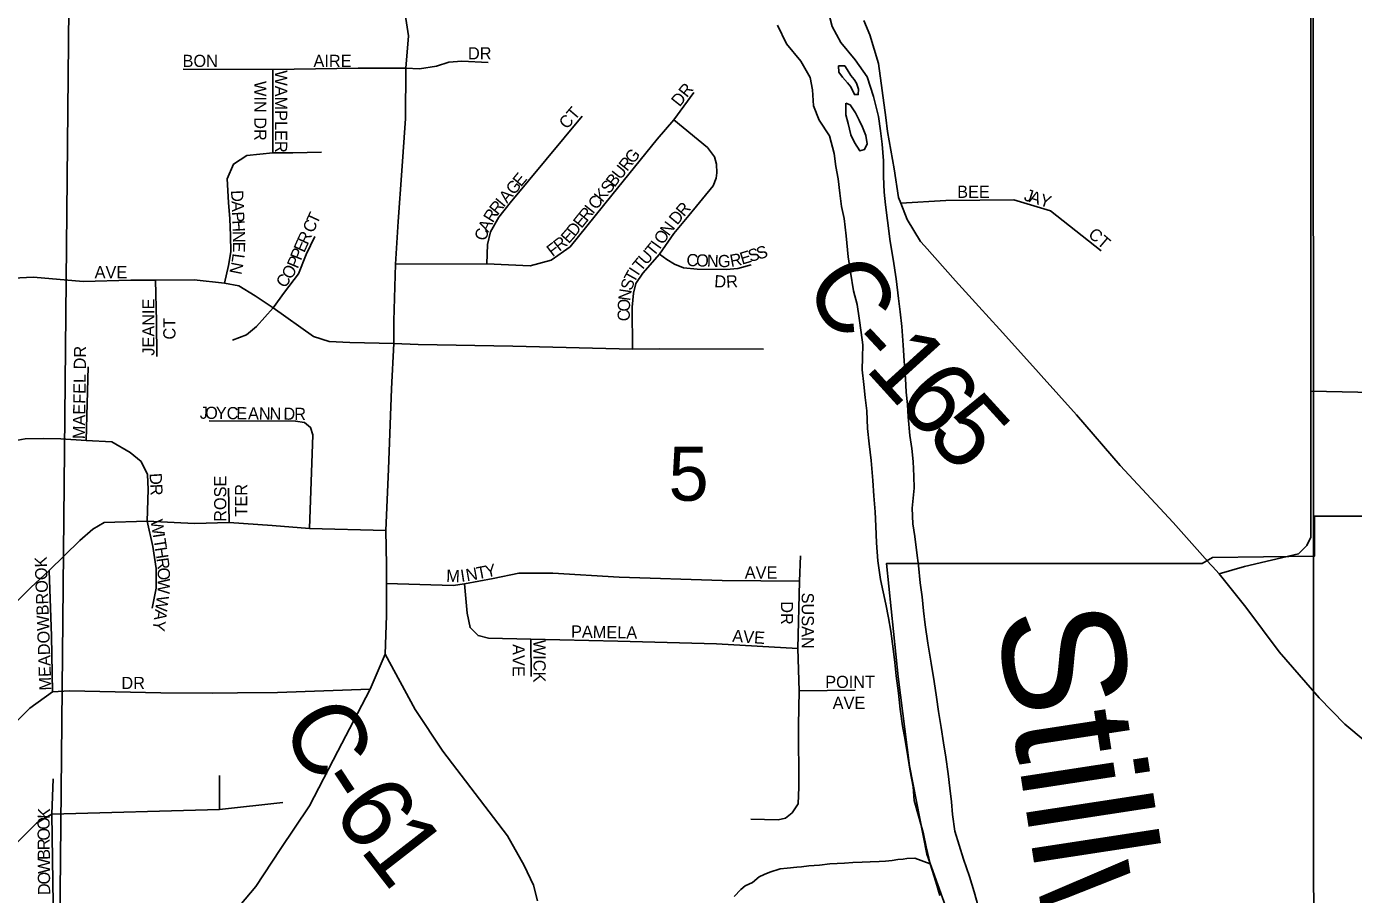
# Model space of a CAD drawing. Extents: x 8.5 to 81.5, y -1.2 to 22.4.
# Drawn here: x 50.196 to 51.227, y 14.998 to 15.672 of the extents above; entities that cross this region are included whole.
import ezdxf

# ---------------------------------------------------------------- set-up
doc = ezdxf.new("R2010")
doc.units = 0
for name, color, linetype in [('GM_X_City_Street', 7, 'Continuous'), ('GM_X_Corporation', 7, 'Continuous'), ('GM_X_County_Road', 7, 'Continuous'), ('GM_X_County_Road_Text', 7, 'Continuous'), ('GM_X_Major_River', 7, 'Continuous'), ('GM_X_Major_River_Text', 7, 'Continuous'), ('GM_X_Minor_River', 7, 'Continuous'), ('GM_X_Section', 7, 'Continuous'), ('GM_X_Section_Text', 7, 'Continuous'), ('GM_X_Township_Road', 7, 'Continuous'), ('GM_X_Township_Subdivision', 7, 'Continuous'), ('GM_X_Township_Subdivision_Text', 7, 'Continuous')]:
    doc.layers.add(name, color=color, linetype=linetype)

msp = doc.modelspace()

# ---------------------------------------------------------------- linework, layer by layer
at = {"layer": 'GM_X_City_Street'}
for points in [[(51.1225, 15.2467), (51.1422, 15.2526), (51.1841, 15.2623), (51.1905, 15.2688), (51.1938, 15.2752), (51.1938, 15.2951), (51.1938, 15.297)], [(51.3735, 15.004), (51.373, 15.0044), (51.3347, 15.0342), (51.3066, 15.0568), (51.27, 15.0866), (51.2359, 15.1168), (51.2201, 15.13), (51.2001, 15.1505), (51.169, 15.1863), (51.1432, 15.2208), (51.1225, 15.2467), (51.1174, 15.2524)]]:
    msp.add_lwpolyline(points, dxfattribs=at)
at = {"layer": 'GM_X_Corporation'}
msp.add_lwpolyline([(51.2945, 15.2917), (51.1966, 15.2917), (51.1966, 15.2606), (51.1174, 15.2595), (51.1092, 15.2548), (50.864, 15.2548), (50.8731, 15.1668), (50.882, 15.0975), (50.8955, 15.0291), (50.9111, 14.985), (50.9207, 14.9475), (50.9238, 14.8897), (50.9254, 14.8296), (50.9211, 14.7826), (50.9101, 14.7376), (50.8975, 14.7193), (50.9131, 14.6619), (50.936, 14.6195), (50.9623, 14.5808), (50.9931, 14.55), (51.0319, 14.511), (51.0505, 14.482), (51.0628, 14.457), (51.0687, 14.4506)], dxfattribs=at)
at = {"layer": 'GM_X_County_Road'}
for points in [[(50.3452, 14.9693), (50.3741, 15.0038), (50.393, 15.0327), (50.4158, 15.0666), (50.438, 15.1089), (50.4531, 15.1383), (50.4631, 15.1572), (50.4747, 15.1845), (50.4756, 15.2145), (50.4756, 15.2394), (50.4756, 15.2537), (50.4751, 15.2804), (50.4773, 15.328), (50.4796, 15.3905), (50.4813, 15.4257), (50.4813, 15.4434), (50.4826, 15.4873), (50.4848, 15.5206), (50.4876, 15.5599), (50.4904, 15.6006), (50.4908, 15.6397), (50.4928, 15.6648), (50.4871, 15.7022)], [(50.8935, 15.5017), (50.8905, 15.5051), (50.8802, 15.5222), (50.8752, 15.5348), (50.8734, 15.5393), (50.87, 15.5615), (50.8649, 15.5905), (50.8635, 15.6013), (50.858, 15.6434), (50.8512, 15.6656), (50.8465, 15.6767)], [(50.9802, 15.4056), (50.9519, 15.4369), (50.9358, 15.4545), (50.9178, 15.4744), (50.8935, 15.5017)], [(51.1174, 15.2524), (51.1158, 15.2541), (51.0867, 15.2867), (51.0457, 15.331), (51.0116, 15.3703), (50.9843, 15.401), (50.9802, 15.4056)], [(50.593, 14.9928), (50.59, 15.0049), (50.5827, 15.0202), (50.5696, 15.0432), (50.5196, 15.1089), (50.4979, 15.1415), (50.4747, 15.1845)]]:
    msp.add_lwpolyline(points, dxfattribs=at)
at = {"layer": 'GM_X_Major_River'}
for points in [[(50.8988, 15.1773), (50.8961, 15.1929), (50.8941, 15.2071), (50.8928, 15.2181), (50.8919, 15.2288), (50.8902, 15.2398), (50.8889, 15.2532), (50.8876, 15.2631), (50.886, 15.2757), (50.8846, 15.2856), (50.8841, 15.2978), (50.8856, 15.3133), (50.8854, 15.3228), (50.8849, 15.3342), (50.8839, 15.3441), (50.8822, 15.3544), (50.881, 15.3689), (50.8804, 15.3784), (50.8795, 15.388), (50.8789, 15.3986), (50.8777, 15.4123), (50.8771, 15.4245), (50.8759, 15.439), (50.8746, 15.4504), (50.8733, 15.4607), (50.8717, 15.4759), (50.8693, 15.4912), (50.8669, 15.5049), (50.865, 15.5213), (50.8633, 15.5335), (50.8624, 15.5434), (50.8619, 15.5556), (50.8617, 15.5678), (50.8608, 15.5807), (50.8595, 15.591), (50.8578, 15.602), (50.854, 15.6177), (50.849, 15.633), (50.8397, 15.6461), (50.8286, 15.6597), (50.822, 15.672), (50.8185, 15.685)], [(50.7795, 15.6732), (50.7864, 15.6586), (50.7975, 15.6451), (50.8049, 15.6324), (50.8066, 15.6229), (50.8075, 15.6103), (50.8118, 15.5992), (50.8199, 15.5872), (50.8235, 15.5735), (50.8248, 15.5632), (50.8265, 15.5537), (50.8278, 15.5426), (50.8291, 15.5323), (50.8312, 15.5228), (50.8328, 15.5094), (50.8344, 15.493), (50.8361, 15.4812), (50.8385, 15.4667), (50.8413, 15.456), (50.843, 15.4454), (50.8443, 15.4343), (50.8456, 15.4248), (50.8454, 15.4149), (50.8452, 15.4054), (50.8465, 15.394), (50.8475, 15.3837), (50.8488, 15.3734), (50.8493, 15.3597), (50.8506, 15.3479), (50.8522, 15.3349), (50.8534, 15.3193), (50.8543, 15.3075), (50.8552, 15.2949), (50.8557, 15.2839), (50.8563, 15.2709), (50.8575, 15.2569), (50.8595, 15.2424), (50.8616, 15.2328), (50.8637, 15.2233), (50.8657, 15.2126), (50.8674, 15.2023), (50.8694, 15.1885), (50.8707, 15.1779), (50.8717, 15.1676), (50.8733, 15.1542), (50.8746, 15.1417), (50.8766, 15.1287), (50.8787, 15.1176), (50.8807, 15.105), (50.8824, 15.0936), (50.8848, 15.0814), (50.8857, 15.0707), (50.8896, 15.0569), (50.8928, 15.0447), (50.8949, 15.0348), (50.898, 15.0214), (50.9023, 15.0076), (50.9055, 14.9969)], [(50.8267, 15.6415), (50.827, 15.6365), (50.83, 15.6326), (50.8337, 15.6284), (50.8363, 15.6253), (50.8392, 15.6192), (50.8422, 15.6191), (50.8423, 15.6233), (50.8409, 15.6279), (50.839, 15.6309), (50.8364, 15.634), (50.8335, 15.6387), (50.8317, 15.6414)], [(50.8317, 15.6414), (50.8267, 15.6415)], [(50.8326, 15.6124), (50.8324, 15.6033), (50.8342, 15.5968), (50.8363, 15.588), (50.8392, 15.5819), (50.8433, 15.5754), (50.8471, 15.5764), (50.8491, 15.5809), (50.8481, 15.5874), (50.8455, 15.5939), (50.843, 15.5993), (50.8401, 15.6051), (50.836, 15.6112)], [(50.836, 15.6112), (50.8326, 15.6124)], [(50.9354, 14.9887), (50.9322, 14.9998), (50.9286, 15.0116), (50.9239, 15.025), (50.9172, 15.0469), (50.9155, 15.0598), (50.9146, 15.0697), (50.9133, 15.0804), (50.912, 15.0915), (50.9103, 15.1044), (50.9083, 15.1155), (50.9066, 15.1273), (50.9046, 15.1399), (50.9029, 15.151), (50.9012, 15.1632), (50.8988, 15.1773)]]:
    msp.add_lwpolyline(points, dxfattribs=at)
at = {"layer": 'GM_X_Minor_River'}
msp.add_lwpolyline([(50.898, 15.0214), (50.8861, 15.0258), (50.88, 15.0255), (50.877, 15.0252), (50.8728, 15.0249), (50.8686, 15.0242), (50.8633, 15.0236), (50.8584, 15.0233), (50.8515, 15.023), (50.8451, 15.0228), (50.8379, 15.0226), (50.8314, 15.0219), (50.82, 15.0214), (50.812, 15.0204), (50.8037, 15.0198), (50.798, 15.0192), (50.7945, 15.0189), (50.7869, 15.0182), (50.7816, 15.0176), (50.7736, 15.0151), (50.769, 15.0133), (50.7652, 15.0115), (50.7601, 15.007), (50.7544, 15.0044), (50.7509, 15.0015), (50.7459, 14.9962)], dxfattribs=at)
at = {"layer": 'GM_X_Section'}
msp.add_lwpolyline([(49.4527, 14.8223), (50.2203, 14.8143), (50.2298, 15.7659), (49.4527, 15.7683)], dxfattribs=at)
for points in [[(50.2298, 15.7659), (51.1955, 15.7645), (51.1961, 14.7442), (50.219, 14.7462), (50.2203, 14.8143)], [(51.1955, 15.7645), (52.2033, 15.7642), (52.1975, 14.7482), (51.1961, 14.7442)]]:
    msp.add_lwpolyline(points, close=True, dxfattribs=at)
at = {"layer": 'GM_X_Township_Road'}
for points in [[(51.1938, 15.297), (51.1938, 15.3886), (51.1938, 15.7549), (51.1938, 15.7639), (51.1938, 15.7681)], [(51.1938, 15.3886), (51.3031, 15.3865)]]:
    msp.add_lwpolyline(points, dxfattribs=at)
at = {"layer": 'GM_X_Township_Subdivision'}
for points in [[(50.5548, 15.6441), (50.5343, 15.645), (50.5241, 15.6443), (50.5145, 15.6413), (50.5013, 15.6392), (50.4908, 15.6397), (50.4536, 15.6397), (50.3873, 15.6387), (50.3177, 15.639)], [(50.3873, 15.6387), (50.3873, 15.5987), (50.3873, 15.5739)], [(50.4826, 15.4873), (50.5537, 15.4876), (50.5872, 15.486), (50.6036, 15.4906), (50.6183, 15.5009), (50.6507, 15.5411), (50.686, 15.5846), (50.6988, 15.5995), (50.7144, 15.6208)], [(50.5537, 15.4876), (50.5542, 15.5026), (50.5566, 15.5124), (50.5629, 15.5238), (50.5719, 15.535), (50.6276, 15.6024)], [(50.6667, 15.4213), (50.6665, 15.4541), (50.6675, 15.4648), (50.6695, 15.4725), (50.6749, 15.4804), (50.6879, 15.4951), (50.699, 15.5111), (50.7106, 15.5251), (50.7295, 15.5482), (50.7319, 15.5543), (50.7322, 15.5584), (50.7321, 15.5651), (50.7304, 15.5708), (50.725, 15.578), (50.6988, 15.5995)], [(50.4252, 15.5743), (50.4029, 15.5738), (50.3873, 15.5739), (50.3673, 15.5717), (50.3568, 15.5652), (50.3519, 15.5538), (50.3529, 15.5352), (50.3541, 15.5226), (50.3545, 15.5097), (50.3547, 15.4969), (50.3531, 15.4864), (50.3499, 15.4727)], [(50.8752, 15.5348), (50.9101, 15.5368), (50.963, 15.5373), (50.9914, 15.5288), (51.0308, 15.4978)], [(50.3562, 15.4283), (50.3669, 15.4324), (50.3747, 15.439), (50.3878, 15.4535), (50.3966, 15.4657), (50.4073, 15.4798), (50.4132, 15.4949), (50.42, 15.5089)], [(50.6879, 15.4951), (50.6936, 15.491), (50.6995, 15.4875), (50.7063, 15.4846), (50.717, 15.4834), (50.7396, 15.4832), (50.7485, 15.484), (50.7591, 15.4868)], [(50.137, 15.4742), (50.2015, 15.4772), (50.24, 15.4738), (50.277, 15.475), (50.2962, 15.475), (50.3262, 15.4753), (50.3499, 15.4727), (50.361, 15.4705), (50.3736, 15.4627), (50.3878, 15.4535), (50.4191, 15.4313), (50.4313, 15.4272), (50.4473, 15.4265), (50.4813, 15.4257), (50.5002, 15.425), (50.5739, 15.4238), (50.6667, 15.4213), (50.6878, 15.4215), (50.7686, 15.4213)], [(50.2974, 15.4156), (50.2971, 15.4428), (50.2962, 15.475)], [(50.2425, 15.3505), (50.2441, 15.4076)], [(50.416, 15.2821), (50.4184, 15.3547), (50.4168, 15.3606), (50.4119, 15.3643), (50.4051, 15.3655), (50.3379, 15.3658)], [(50.0433, 15.3241), (50.0541, 15.3144), (50.0666, 15.3066), (50.0791, 15.3022), (50.0883, 15.3024), (50.0988, 15.308), (50.1336, 15.3269), (50.1605, 15.3427), (50.1808, 15.3491), (50.195, 15.3516), (50.2089, 15.3519), (50.2228, 15.3516), (50.2425, 15.3505), (50.2623, 15.3494), (50.2767, 15.341), (50.2851, 15.334), (50.2901, 15.3241), (50.2906, 15.3122), (50.2898, 15.2876)], [(50.3534, 15.2866), (50.3531, 15.3133)], [(49.9768, 15.0149), (50.0523, 15.089), (50.0959, 15.1337), (50.1326, 15.1704), (50.1995, 15.2363), (50.2138, 15.2494), (50.2374, 15.2728), (50.2475, 15.2815), (50.2564, 15.2867), (50.2898, 15.2876), (50.3267, 15.286), (50.3534, 15.2866), (50.3868, 15.2844), (50.416, 15.2821), (50.4751, 15.2804)], [(50.2898, 15.2876), (50.2942, 15.2681), (50.2969, 15.2509), (50.2969, 15.2356), (50.2937, 15.22)], [(50.7974, 15.2609), (50.7965, 15.241), (50.7953, 15.1888), (50.7963, 15.1559), (50.7958, 15.1292), (50.7961, 15.0811), (50.7954, 15.068), (50.7908, 15.0611), (50.7857, 15.0569), (50.78, 15.0557), (50.7587, 15.0561)], [(50.2163, 15.1551), (50.2156, 15.1983), (50.2138, 15.2494)], [(50.4756, 15.2394), (50.5274, 15.2378), (50.5362, 15.2389), (50.5587, 15.2433), (50.5786, 15.2474), (50.605, 15.2474), (50.6565, 15.2441), (50.7364, 15.2417), (50.7965, 15.241)], [(50.5362, 15.2389), (50.5384, 15.2163), (50.5407, 15.2051), (50.5469, 15.1988), (50.5549, 15.1969), (50.5879, 15.196), (50.6555, 15.1946), (50.7321, 15.1925), (50.7953, 15.1888)], [(50.5879, 15.196), (50.5882, 15.1671)], [(50.0242, 14.968), (50.1215, 15.0647), (50.1629, 15.1069), (50.1986, 15.1425), (50.2163, 15.1551), (50.2296, 15.156), (50.3005, 15.1544), (50.3402, 15.1542), (50.36, 15.1544)], [(50.36, 15.1544), (50.3911, 15.1547), (50.4631, 15.1572)], [(50.7963, 15.1559), (50.8397, 15.1564)], [(50.3461, 15.0636), (50.3461, 15.0902)], [(50.2164, 14.9709), (50.2167, 14.9903), (50.2157, 15.0601), (50.2167, 15.0876)], [(49.721, 14.821), (49.7244, 14.8955), (49.7293, 14.8972), (49.8298, 14.8955), (49.9335, 14.8939), (50.0049, 14.8923), (50.0389, 14.8923), (50.0487, 14.8955), (50.0584, 14.902), (50.0707, 14.9213), (50.2038, 15.053), (50.2157, 15.0601), (50.3461, 15.0636), (50.3952, 15.0691)]]:
    msp.add_lwpolyline(points, dxfattribs=at)

# ---------------------------------------------------------------- texts
at = {"layer": 'GM_X_County_Road_Text'}
for s, rotation, p in [('C', 303.2268, (50.7987, 15.4704)), ('-', 313.0785, (50.8308, 15.4229)), ('1', 312.2135, (50.8466, 15.4061)), ('6', 312.3493, (50.8702, 15.38)), ('5', 312.3719, (50.8938, 15.3541)), ('C', 298.0454, (50.3929, 15.1303)), ('-', 303.4177, (50.4178, 15.0841)), ('6', 306.3501, (50.4324, 15.062)), ('1', 307.8514, (50.4542, 15.0325))]:
    msp.add_text(s, height=0.0568, rotation=rotation, dxfattribs=at).set_placement(p)
at = {"layer": 'GM_X_Major_River_Text'}
msp.add_text('Stillwater', height=0.09478, rotation=278.71, dxfattribs=at).set_placement((50.949, 15.216))
at = {"layer": 'GM_X_Section_Text'}
msp.add_text('5', height=0.0419, rotation=0, dxfattribs=at).set_placement((50.6948, 15.3036))
at = {"layer": 'GM_X_Township_Subdivision_Text'}
for s, rotation, p in [('BON', 0, (50.3173, 15.6406)), ('AIRE', 0, (50.419, 15.6406)), ('DR', 0, (50.539, 15.6465)), ('WAMPLER', 270, (50.3891, 15.638)), ('WIN DR', 270, (50.373, 15.6297)), ('DR', 51.3437, (50.7034, 15.6091)), ('CT', 49.3961, (50.6159, 15.5917)), ('G', 51.3334, (50.6673, 15.5648)), ('U', 51.3334, (50.6574, 15.5525)), ('R', 51.3326, (50.6626, 15.559)), ('E', 50.1839, (50.5801, 15.547)), ('B', 51.3418, (50.6527, 15.5466)), ('D', 272.6452, (50.3549, 15.5447)), ('A', 50.1692, (50.5694, 15.5342)), ('G', 50.1909, (50.5748, 15.5406)), ('K', 51.3334, (50.6434, 15.5349)), ('S', 51.3536, (50.6486, 15.5414)), ('BEE', 0, (50.919, 15.5389)), ('J', 342.2287, (50.9703, 15.5372)), ('A', 342.2481, (50.9743, 15.5359)), ('A', 272.6532, (50.3553, 15.5364)), ('R', 51.5905, (50.5621, 15.5251)), ('I', 50.2616, (50.5668, 15.531)), ('I', 51.347, (50.6361, 15.5258)), ('C', 51.3326, (50.6387, 15.5291)), ('R', 49.3144, (50.7068, 15.5237)), ('Y', 342.2697, (50.9822, 15.5334)), ('P', 272.651, (50.3556, 15.5281)), ('T', 65.3212, (50.4218, 15.5178)), ('R', 58.0615, (50.5583, 15.519)), ('E', 51.3182, (50.6272, 15.5147)), ('R', 51.3418, (50.6314, 15.5199)), ('D', 50.5107, (50.7015, 15.5173)), ('H', 272.6452, (50.3559, 15.5214)), ('N', 271.3332, (50.3563, 15.5131)), ('R', 65.347, (50.4145, 15.5019)), ('C', 65.3249, (50.4187, 15.511)), ('C', 74.9387, (50.553, 15.505)), ('A', 64.0508, (50.5548, 15.5117)), ('E', 48.5036, (50.6173, 15.5028)), ('D', 51.3146, (50.622, 15.5082)), ('O', 55.438, (50.6904, 15.502)), ('N', 53.2044, (50.695, 15.5087)), ('CT', 319.3961, (51.0201, 15.5094)), ('E', 269.1257, (50.3565, 15.5049)), ('E', 65.8794, (50.4118, 15.4958)), ('F', 37.6402, (50.6047, 15.4928)), ('R', 38.094, (50.61, 15.4969)), ('T', 50.7343, (50.6832, 15.4927)), ('I', 54.5991, (50.6879, 15.4984)), ('L', 262.0515, (50.3563, 15.4961)), ('P', 67.1863, (50.4067, 15.4834)), ('P', 68.0427, (50.4093, 15.4897)), ('T', 50.3588, (50.6733, 15.4811)), ('U', 48.8202, (50.6775, 15.4862)), ('C', 357.9113, (50.7086, 15.486)), ('O', 357.2893, (50.716, 15.4858)), ('N', 358.1463, (50.7245, 15.4854)), ('G', 359.8128, (50.7331, 15.4851)), ('R', 10.7443, (50.7434, 15.4852)), ('E', 16.9156, (50.7519, 15.4869)), ('S', 17.2496, (50.7583, 15.4889)), ('S', 17.2514, (50.7647, 15.4908)), ('AVE', 0, (50.249, 15.4765)), ('N', 258.8487, (50.3554, 15.4896)), ('O', 58.0754, (50.4015, 15.4749)), ('T', 61.0887, (50.668, 15.4722)), ('I', 56.4555, (50.6712, 15.4779)), ('C', 54.019, (50.3967, 15.4682)), ('S', 71.3404, (50.6661, 15.4663)), ('D', 355.8443, (50.7301, 15.4696)), ('R', 3.6338, (50.7398, 15.469)), ('N', 81.975, (50.665, 15.4585)), ('JEANIE', 90, (50.2955, 15.4163)), ('C', 89.6114, (50.6647, 15.443)), ('O', 87.6823, (50.6647, 15.4504)), ('CT', 90, (50.3118, 15.4288)), ('MAEFEL DR', 89.2659, (50.2415, 15.3514)), ('J', 359.2571, (50.3306, 15.3673)), ('O', 359.272, (50.3348, 15.3672)), ('Y', 359.2568, (50.3431, 15.3671)), ('C', 359.2699, (50.3515, 15.367)), ('E', 359.2623, (50.359, 15.3669)), ('A', 359.272, (50.3681, 15.3668)), ('N', 359.2568, (50.3765, 15.3667)), ('N', 359.272, (50.3848, 15.3666)), ('D', 359.2568, (50.3956, 15.3665)), ('R', 359.2699, (50.404, 15.3664)), ('D', 273.6309, (50.2916, 15.3248)), ('ROSE', 90, (50.3513, 15.2872)), ('R', 272.3809, (50.2921, 15.3165)), ('TER', 90, (50.3675, 15.2913)), ('W', 278.7768, (50.2924, 15.2883)), ('I', 278.7794, (50.294, 15.2776)), ('T', 278.7752, (50.2947, 15.2735)), ('H', 278.7761, (50.2957, 15.2669)), ('MEADOWBROOK', 92.0456, (50.2155, 15.1563)), ('R', 277.821, (50.2969, 15.2587)), ('Y', 12.5017, (50.5534, 15.2438)), ('O', 271.9456, (50.2979, 15.2515)), ('M', 358.1054, (50.522, 15.2406)), ('I', 8.7206, (50.5339, 15.2404)), ('N', 10.1923, (50.5382, 15.241)), ('T', 10.893, (50.5466, 15.2425)), ('AVE', 0, (50.754, 15.2431)), ('W', 267.7967, (50.2982, 15.2434)), ('W', 262.3265, (50.2975, 15.2303)), ('DR', 270, (50.7821, 15.2255)), ('SUSAN', 270, (50.7982, 15.2322)), ('A', 262.2378, (50.2961, 15.2196)), ('Y', 262.2356, (50.295, 15.2113)), ('PAMELA', 358.9955, (50.619, 15.1973)), ('AVE', 356.0494, (50.7441, 15.194)), ('WICK', 270, (50.5899, 15.1955)), ('AVE', 270, (50.5736, 15.1922)), ('DR', 0, (50.2698, 15.1573)), ('POINT', 0, (50.8165, 15.1581)), ('AVE', 0, (50.8223, 15.1418)), ('K', 86.8287, (50.214, 15.0562)), ('O', 90.4372, (50.2141, 15.048)), ('O', 90.4437, (50.2142, 15.0396)), ('R', 90.4335, (50.2142, 15.0321)), ('B', 90.4372, (50.2143, 15.0246)), ('W', 90.4485, (50.2144, 15.0138)), ('O', 90.432, (50.2144, 15.0055)), ('D', 90.432, (50.2145, 14.9972))]:
    msp.add_text(s, height=0.00947, rotation=rotation, dxfattribs=at).set_placement(p)

doc.saveas('drawing.dxf')
